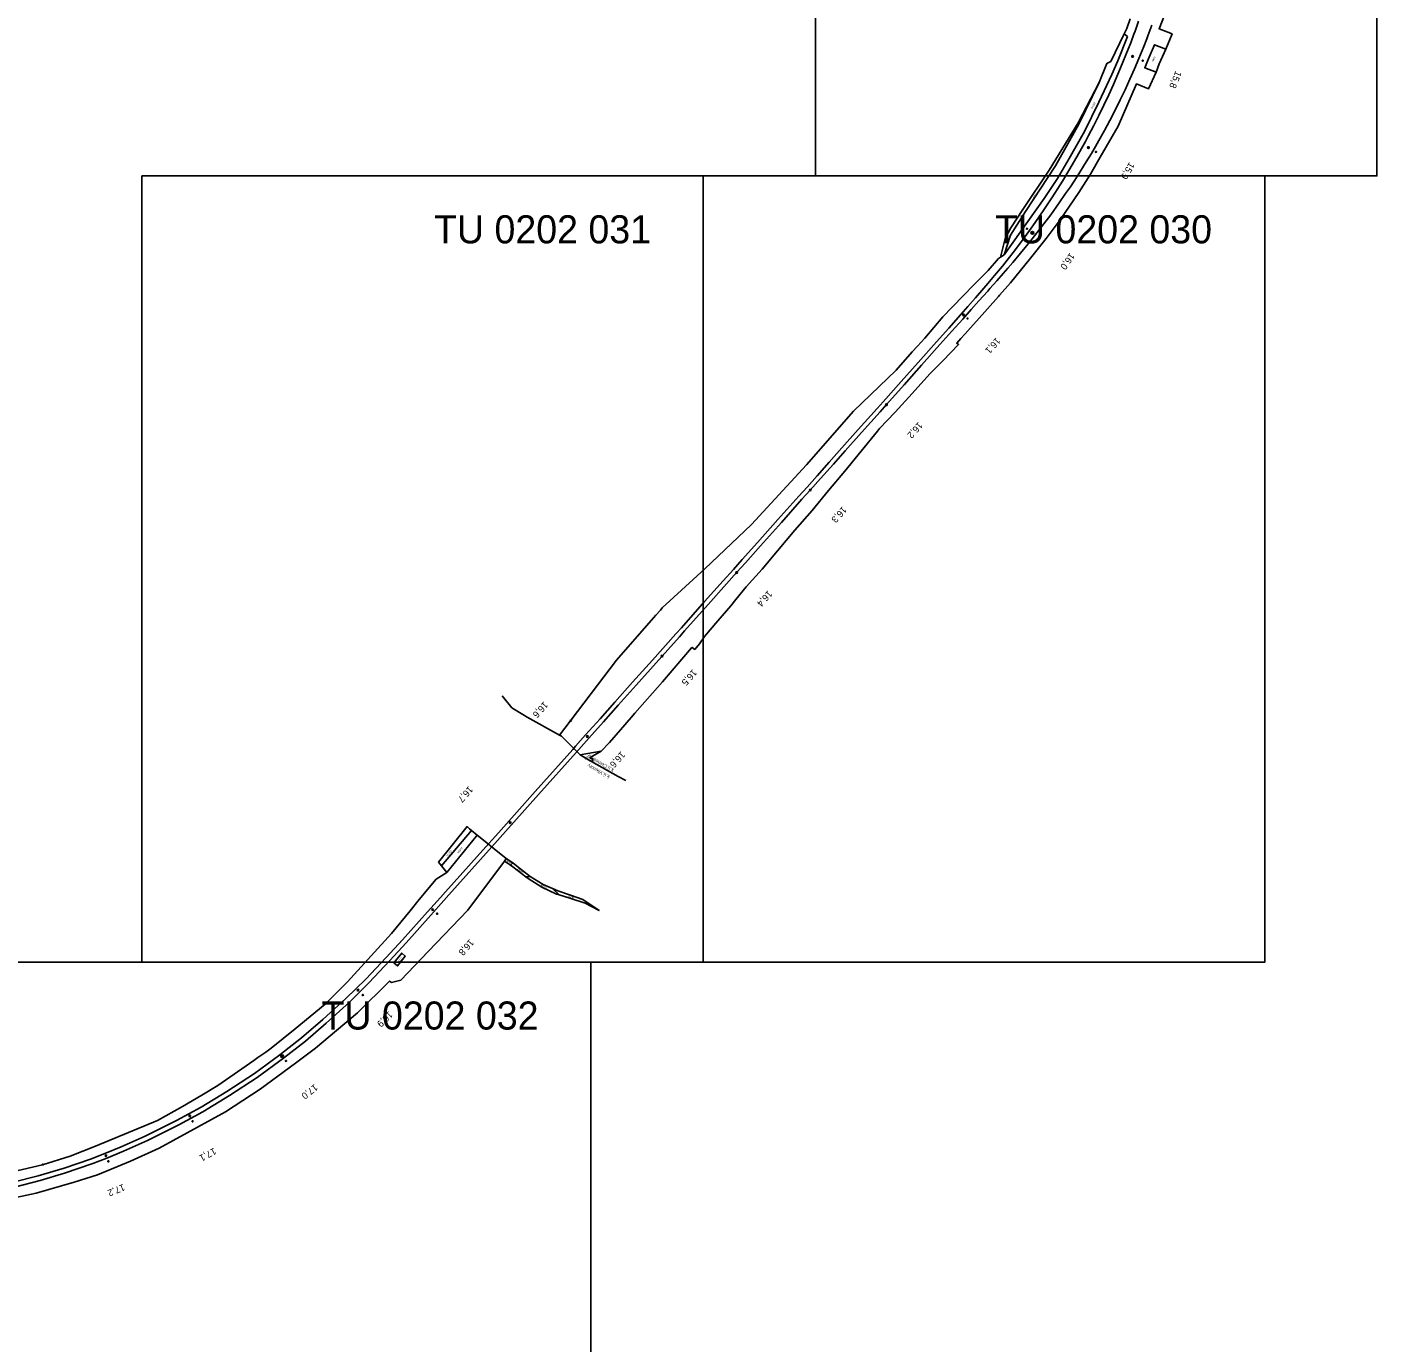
# Model space of a CAD drawing. Extents: x -768800 to -748700, y -1061452 to -1051366.
# Drawn here: x -752402 to -751200, y -1058839 to -1057667 of the extents above; entities that cross this region are included whole.
import ezdxf

# ---------------------------------------------------------------- set-up
doc = ezdxf.new("R2010")
doc.units = 0
for name, color, linetype in [('Vrstva 1', 7, 'Continuous'), ('Vrstva 2', 7, 'Continuous'), ('Vrstva 53', 7, 'Continuous'), ('Vrstva 55', 7, 'Continuous'), ('Vrstva 57', 7, 'Continuous'), ('Vrstva 7', 7, 'Continuous')]:
    doc.layers.add(name, color=color, linetype=linetype)

msp = doc.modelspace()

# ---------------------------------------------------------------- linework, layer by layer
at = {"layer": 'Vrstva 1'}
msp.add_line((-751946.7, -1058350.7), (-751990.8, -1058400.1), dxfattribs=at)
for points in [[(-751700, -1057800), (-751700, -1057100), (-751200, -1057100), (-751200, -1057800), (-751700, -1057800)], [(-751412.3, -1057662.3), (-751415.8, -1057671.9), (-751416.2, -1057673), (-751419.3, -1057681.4), (-751423, -1057690.7), (-751426.8, -1057700.2), (-751430.7, -1057709.4), (-751434.7, -1057718.7), (-751438.9, -1057727.9), (-751443.2, -1057736.9), (-751447.6, -1057746.1), (-751452.2, -1057755.1), (-751456.9, -1057764.1), (-751459.7, -1057769.4), (-751463.1, -1057775.5), (-751467.3, -1057782.9)], [(-751400.6, -1057665.8), (-751404.1, -1057675.3), (-751405.1, -1057677.8), (-751407.8, -1057684.8), (-751412, -1057695.3), (-751416, -1057704.6)], [(-751416, -1057704.6), (-751420.1, -1057713.9), (-751424.4, -1057723.3), (-751428.7, -1057732.3), (-751433.3, -1057741.5), (-751437.9, -1057750.5), (-751442.8, -1057759.6), (-751447.7, -1057768.5), (-751450.7, -1057773.7), (-751454.4, -1057780), (-751458.9, -1057787.5), (-751467.1, -1057800.4), (-751473.1, -1057809.6), (-751477.3, -1057815.7), (-751483, -1057823.9), (-751490.6, -1057834.5), (-751498.8, -1057845.4), (-751509.3, -1057858.7), (-751513.3, -1057863.7), (-751517.5, -1057868.8), (-751524.3, -1057876.9), (-751528.9, -1057882.2), (-751532.9, -1057886.8), (-751538.7, -1057893.5), (-751544.7, -1057900.3), (-751546.6, -1057902.5), (-751554.5, -1057911.3), (-751561.3, -1057918.9), (-751568.9, -1057927.5), (-751578.5, -1057938.2), (-751589.2, -1057950.2), (-751605.6, -1057968.6), (-751621.1, -1057985.9), (-751636.8, -1058003.6), (-751642.5, -1058010), (-751659, -1058028.4), (-751673.5, -1058044.7), (-751684.1, -1058056.6), (-751695.7, -1058069.5), (-751704.8, -1058079.7), (-751712.1, -1058087.9), (-751730.4, -1058108.4), (-751749, -1058129.2), (-751762.4, -1058144.3), (-751770.1, -1058152.9), (-751779.3, -1058163.2), (-751795.6, -1058181.5), (-751816.7, -1058205), (-751821.3, -1058210.3), (-751842, -1058233.4), (-751859.9, -1058253.4), (-751875.7, -1058271.1), (-751889, -1058286), (-751901.9, -1058300.5), (-751910.9, -1058310.5)], [(-751467.3, -1057782.9), (-751474.3, -1057795), (-751480.1, -1057804.5), (-751484.3, -1057811.3), (-751489.5, -1057819.5), (-751496.7, -1057830.3), (-751504.4, -1057841.4), (-751509.4, -1057848.5), (-751514.2, -1057855), (-751522, -1057865.4), (-751529.3, -1057874.9), (-751533.6, -1057880.2), (-751540.5, -1057888.5), (-751546.6, -1057895.8), (-751550.1, -1057899.9), (-751557.5, -1057908.4), (-751564.3, -1057916.2), (-751570.5, -1057923.3), (-751581.4, -1057935.5), (-751592.2, -1057947.6), (-751608.6, -1057966), (-751623.8, -1057983.1), (-751639.8, -1058001), (-751645.2, -1058007), (-751662, -1058025.8), (-751676.5, -1058042.1), (-751687.9, -1058054.9), (-751698.7, -1058067), (-751707.6, -1058077), (-751714.9, -1058085.1), (-751733.5, -1058105.9), (-751751.8, -1058126.4), (-751765.3, -1058141.6), (-751773.1, -1058150.3), (-751782.2, -1058160.5), (-751798.8, -1058179), (-751819.5, -1058202.2), (-751824.3, -1058207.6), (-751845.3, -1058231), (-751863, -1058250.8), (-751878.7, -1058268.5), (-751891.9, -1058283.2), (-751904.8, -1058297.6), (-751913.8, -1058307.7)], [(-752300, -1058500), (-752300, -1057800), (-751800, -1057800), (-751800, -1058500), (-752300, -1058500)], [(-751800, -1058500), (-751800, -1057800), (-751300, -1057800), (-751300, -1058500), (-751800, -1058500)], [(-751913.8, -1058307.7), (-751916.3, -1058310.5), (-751949.7, -1058348)], [(-751910.9, -1058310.5), (-751913.3, -1058313.2), (-751946.7, -1058350.7)], [(-751949.7, -1058348), (-751982.4, -1058384.7), (-751993.7, -1058397.3), (-752029.5, -1058437.4), (-752034, -1058442.5), (-752045.5, -1058455.3), (-752067.9, -1058480.2), (-752082.3, -1058495.8), (-752100.6, -1058515), (-752118.3, -1058532.4), (-752138.7, -1058551.1), (-752157.7, -1058567.3), (-752177.1, -1058582.6), (-752199.7, -1058599), (-752224.3, -1058615.2), (-752247.2, -1058629), (-752269, -1058640.9), (-752297.1, -1058654.9), (-752318.3, -1058664.4), (-752332.9, -1058670.4), (-752345.8, -1058675.4), (-752369.1, -1058683.4), (-752392.4, -1058690.3), (-752414.6, -1058696)], [(-751990.8, -1058400.1), (-752026.5, -1058440), (-752031, -1058445.1), (-752042.7, -1058458.1), (-752064.7, -1058482.8), (-752079, -1058498.5), (-752097.8, -1058518.3), (-752115.1, -1058535.5), (-752135.7, -1058554.4), (-752154.3, -1058570.2), (-752173.7, -1058585.5), (-752197.3, -1058602.6), (-752222, -1058618.8), (-752245.7, -1058633.1), (-752267.2, -1058644.9), (-752295.1, -1058658.7), (-752316.4, -1058668.2), (-752331.3, -1058674.4), (-752343.7, -1058679.1), (-752368.9, -1058687.8), (-752390.5, -1058694.3), (-752414.5, -1058700.5)], [(-752600, -1059000), (-752600, -1058500), (-751900, -1058500), (-751900, -1059000), (-752600, -1059000)]]:
    msp.add_lwpolyline(points, dxfattribs=at)
at = {"layer": 'Vrstva 53'}
for p, q in [((-751918.1, -1058285), (-751918, -1058284.9)), ((-752388.3, -1058680.3), (-752388.2, -1058680.2))]:
    msp.add_line(p, q, dxfattribs=at)
for points in [[(-751383, -1057640.6), (-751394, -1057668.9), (-751382.5, -1057673.5), (-751388.2, -1057687), (-751393.9, -1057700.3), (-751396.7, -1057707.6), (-751403.4, -1057722.3), (-751414.2, -1057718.1), (-751430.5, -1057755.7), (-751446.4, -1057783.4), (-751455.2, -1057798.3), (-751465.4, -1057814.8), (-751482.3, -1057839.2), (-751494.6, -1057855.6), (-751508.6, -1057873.3), (-751526.4, -1057895.1), (-751536.2, -1057906.1), (-751537.2, -1057907.2), (-751556.7, -1057929.3), (-751559.6, -1057932.5), (-751566.8, -1057940.6), (-751570.6, -1057944.8), (-751574.2, -1057949), (-751572.7, -1057950.1), (-751586.6, -1057964.5), (-751598.1, -1057976.3), (-751614, -1057993.6), (-751629.1, -1058010.2), (-751643.1, -1058024.8), (-751644.7, -1058027.3), (-751659.5, -1058045.1), (-751673.9, -1058062.8), (-751688.4, -1058080.1), (-751702.9, -1058097.8), (-751718.5, -1058115.4), (-751734, -1058133.9), (-751747.6, -1058150.2), (-751761.7, -1058165.7), (-751770.9, -1058177), (-751775.4, -1058182.7), (-751787.1, -1058196), (-751799, -1058210.1), (-751803.4, -1058216.6), (-751807.6, -1058221.6), (-751809.8, -1058219.7), (-751810.4, -1058220.2), (-751836.3, -1058250.3), (-751860.9, -1058278.4), (-751864.1, -1058282.1), (-751873.7, -1058293.2), (-751883.5, -1058304.5), (-751891, -1058312), (-751898.6, -1058316.5), (-751900.9, -1058318.1), (-751898.2, -1058319.6), (-751899.6, -1058321.2), (-751909.6, -1058315.4), (-751915.6, -1058309.4), (-751926.2, -1058298.9), (-751928.1, -1058297.8)], [(-751928.1, -1058297.8), (-751923.4, -1058291.7), (-751877.4, -1058231.2), (-751844.4, -1058193.4), (-751842.3, -1058190.9), (-751838.2, -1058186.5), (-751836.6, -1058184.4), (-751798.5, -1058149.7), (-751757.2, -1058110.2), (-751708, -1058057.1), (-751666.1, -1058009.3), (-751628.2, -1057972.9), (-751614.1, -1057956.7), (-751609.1, -1057951.4), (-751606.1, -1057948.1), (-751602.7, -1057944.5), (-751586.8, -1057925.4), (-751578.3, -1057916.7), (-751568.3, -1057906.5), (-751559, -1057897), (-751546.3, -1057884.1), (-751537, -1057873.6), (-751535.2, -1057872.4), (-751531.2, -1057855.8), (-751526.1, -1057846.2), (-751515.3, -1057829.9), (-751491.9, -1057794.9), (-751466.2, -1057752.6), (-751447.5, -1057716.7), (-751440.7, -1057699.8), (-751437.1, -1057698.1), (-751425.3, -1057673.6), (-751422.9, -1057668.6), (-751419.8, -1057660.1)], [(-752035.8, -1058411), (-752010.3, -1058379.3), (-752008.3, -1058381.2), (-752006.3, -1058382.9), (-752001.5, -1058386.8), (-751994.3, -1058392.6), (-751986.2, -1058399.1), (-751975.6, -1058407.6), (-751969.7, -1058411.6), (-751967.8, -1058412.9), (-751954.2, -1058423.7), (-751942.6, -1058430.7), (-751934.3, -1058434.5), (-751929.6, -1058436.6), (-751918.2, -1058440.3), (-751907.2, -1058444.3), (-751892.8, -1058454), (-751905.3, -1058447.6), (-751918.7, -1058442.9), (-751928.2, -1058440.1), (-751930.6, -1058439.3), (-751943.8, -1058433.1), (-751956, -1058425.6), (-751957.9, -1058424.1), (-751969.7, -1058415.1), (-751971.7, -1058413.7), (-751977.1, -1058410.1), (-752009.8, -1058453.6), (-752045, -1058490.5), (-752069.3, -1058516), (-752077.8, -1058518.2), (-752079.4, -1058516.8), (-752107.9, -1058545), (-752145.4, -1058576.5), (-752163.2, -1058589.8), (-752194.5, -1058613.2), (-752225.6, -1058633.2), (-752284.5, -1058665.5), (-752310.1, -1058677.2), (-752339.6, -1058689.3), (-752360.4, -1058695.9), (-752394.1, -1058705.8), (-752443, -1058716)], [(-752415.2, -1058686.6), (-752388.4, -1058680.4), (-752363.8, -1058672.7), (-752341.2, -1058663.9), (-752286.2, -1058641), (-752263.8, -1058628.6), (-752246.6, -1058618.3), (-752232.3, -1058609.8), (-752200.4, -1058587.4), (-752196.6, -1058584.8), (-752189.6, -1058580), (-752184.9, -1058576.7), (-752163.6, -1058559.3), (-752136.6, -1058537.3), (-752116.7, -1058517.4), (-752077.6, -1058474.5), (-752061, -1058454.2), (-752052.9, -1058444.3), (-752038, -1058426.1), (-752028.3, -1058420.1), (-752033.1, -1058414.3), (-752035.8, -1058411)]]:
    msp.add_lwpolyline(points, dxfattribs=at)
for centre in [(-751918, -1058285), (-752388.2, -1058680.2)]:
    msp.add_circle(centre, 0.499, dxfattribs=at)
at = {"layer": 'Vrstva 55'}
for p, q in [((-751970.6, -1058273.4), (-751979.2, -1058263)), ((-751909.6, -1058315.4), (-751891, -1058312)), ((-752033.1, -1058414.3), (-752006.3, -1058382.9)), ((-752028.3, -1058420.1), (-752001.5, -1058386.8)), ((-751977.1, -1058410.1), (-751975.6, -1058407.6)), ((-751971.7, -1058413.7), (-751969.7, -1058411.6)), ((-751957.9, -1058424.1), (-751954.2, -1058423.7)), ((-751928.2, -1058440.1), (-751934.3, -1058434.5))]:
    msp.add_line(p, q, dxfattribs=at)
for points in [[(-751425.3, -1057673.6), (-751422.2, -1057675.9), (-751430.9, -1057697.5), (-751436.2, -1057709.6), (-751447.6, -1057734.3), (-751460.6, -1057760.5), (-751474.1, -1057784.4), (-751484.6, -1057802.2), (-751496.3, -1057820), (-751532.1, -1057870.1)], [(-751396.7, -1057707.6), (-751406.8, -1057703.6), (-751403.9, -1057696.3), (-751398.2, -1057683.2), (-751388.2, -1057687)], [(-751526.4, -1057852.6), (-751513.1, -1057831.6), (-751486.3, -1057790.9), (-751465.6, -1057753.8), (-751447.5, -1057716.7)], [(-751535.2, -1057872.4), (-751532.1, -1057870.1), (-751526.4, -1057852.6)], [(-751970.6, -1058273.4), (-751960.7, -1058279.6), (-751956.9, -1058282), (-751928.1, -1058297.8), (-751926.2, -1058298.9), (-751919, -1058306), (-751909.6, -1058315.4), (-751900.7, -1058320.6), (-751899.6, -1058321.2), (-751875.9, -1058334.6), (-751869, -1058338.1)], [(-752075.6, -1058500.6), (-752072.2, -1058503.3), (-752065.4, -1058494.5), (-752068.6, -1058491.9), (-752075.6, -1058500.6)]]:
    msp.add_lwpolyline(points, dxfattribs=at)
at = {"layer": 'Vrstva 7'}
for p, q in [((-751408.6, -1057697.3), (-751408.6, -1057697.4)), ((-751450.2, -1057778.5), (-751450.2, -1057778.6)), ((-751511.6, -1057846.9), (-751511.7, -1057847)), ((-751564.6, -1057926.8), (-751564.7, -1057926.9)), ((-752036.9, -1058456.7), (-752037, -1058456.8)), ((-752103.2, -1058529.1), (-752103.3, -1058529.2)), ((-752171.6, -1058587.9), (-752171.7, -1058587.9)), ((-752254.7, -1058641.7), (-752254.8, -1058641.7)), ((-752329.8, -1058677.3), (-752329.9, -1058677.3))]:
    msp.add_line(p, q, dxfattribs=at)
for centre, radius in [((-751417.7, -1057693.6), 0.75), ((-751408.6, -1057697.3), 0.5), ((-751457, -1057774.7), 0.75), ((-751450.2, -1057778.6), 0.5), ((-751511.7, -1057847), 0.5), ((-751506.9, -1057850.6), 1.25), ((-751506.9, -1057850.6), 0.752), ((-751568.2, -1057923.7), 0.75), ((-751564.6, -1057926.9), 0.5), ((-751636.9, -1058003.7), 0.75), ((-751704.7, -1058079.6), 0.75), ((-751770.3, -1058153.1), 0.75), ((-751836.7, -1058227.5), 0.75), ((-751903.2, -1058299), 0.75), ((-751971.9, -1058375.8), 0.75), ((-752041, -1058453.2), 0.75), ((-752037, -1058456.8), 0.5), ((-752107.5, -1058524.9), 0.75), ((-752103.2, -1058529.2), 0.5), ((-752175, -1058583.7), 1.25), ((-752175, -1058583.7), 0.752), ((-752171.6, -1058587.9), 0.5), ((-752257.3, -1058637), 0.75), ((-752254.8, -1058641.7), 0.5), ((-752331.9, -1058672.3), 0.75), ((-752329.8, -1058677.3), 0.5)]:
    msp.add_circle(centre, radius, dxfattribs=at)

# ---------------------------------------------------------------- texts
at = {"layer": 'Vrstva 2'}
for s, p in [('TU 0202 031', (-752039.8, -1057860)), ('TU 0202 030', (-751540.2, -1057860)), ('TU 0202 032', (-752140, -1058560))]:
    msp.add_text(s, height=25, dxfattribs=at).set_placement(p)
at = {"layer": 'Vrstva 55'}
for s, p in [('k.ú.Všenory', (-751883.1, -1058334)), ('k.ú.Černošice', (-751879.4, -1058328))]:
    msp.add_text(s, height=3, rotation=150.7636, dxfattribs=at).set_placement(p)
at = {"layer": 'Vrstva 57'}
for s, rotation, p in [('6186', 243.9195, (-751398.5, -1057693.5)), ('2625/2', 242.0236, (-751451.8, -1057734.1)), ('2626/5', 236.8388, (-751504.1, -1057815.5)), ('5845/6', 223.2369, (-751901.3, -1058314.5)), ('2120/4', 229.7313, (-752015.1, -1058397.3)), ('1927/3', 230.2549, (-752024.6, -1058400.1)), ('1926/1', 144.7468, (-751970.7, -1058411.8)), ('1926/6', 142.3465, (-751960.1, -1058419.9)), ('1926/8', 152.293, (-751938.4, -1058433.4)), ('1926/7', 159.7441, (-751914.5, -1058442.3)), ('2113', 228.0671, (-752068.7, -1058495.4))]:
    msp.add_text(s, height=1.5, rotation=rotation, dxfattribs=at).set_placement(p)
at = {"layer": 'Vrstva 7'}
for s, rotation, p in [('15,8', 247.9859, (-751379.3, -1057706)), ('15,9', 239.6419, (-751420.5, -1057787.3)), ('16,0', 234.5938, (-751473.4, -1057868)), ('16,1', 228.5517, (-751539.1, -1057943.4)), ('16,2', 228.2865, (-751608.4, -1058018.6)), ('16,3', 228.2917, (-751676, -1058093.8)), ('16,4', 228.2779, (-751742.3, -1058168.6)), ('16,5', 228.2249, (-751809.4, -1058238.8)), ('16,6', 228.2403, (-751942, -1058267.5)), ('16,6', 228.2457, (-751873.3, -1058311.9)), ('16,7', 228.2656, (-752008.8, -1058342.8)), ('16,8', 228.166, (-752008, -1058479.1)), ('16,9', 224.5803, (-752080, -1058543.2)), ('17,0', 218.2557, (-752146.2, -1058608.2)), ('17,1', 208.798, (-752235.8, -1058665)), ('17,2', 202.4075, (-752316.6, -1058697.3))]:
    msp.add_text(s, height=6, rotation=rotation, dxfattribs=at).set_placement(p)

doc.saveas('drawing.dxf')
